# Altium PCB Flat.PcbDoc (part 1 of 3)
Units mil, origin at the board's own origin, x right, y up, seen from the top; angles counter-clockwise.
Board outline 3858.27 x 3228.35 mil, 2 copper layers (Top Layer, Bottom Layer); 95 components, 49 nets, 285 pads, 121 vias.
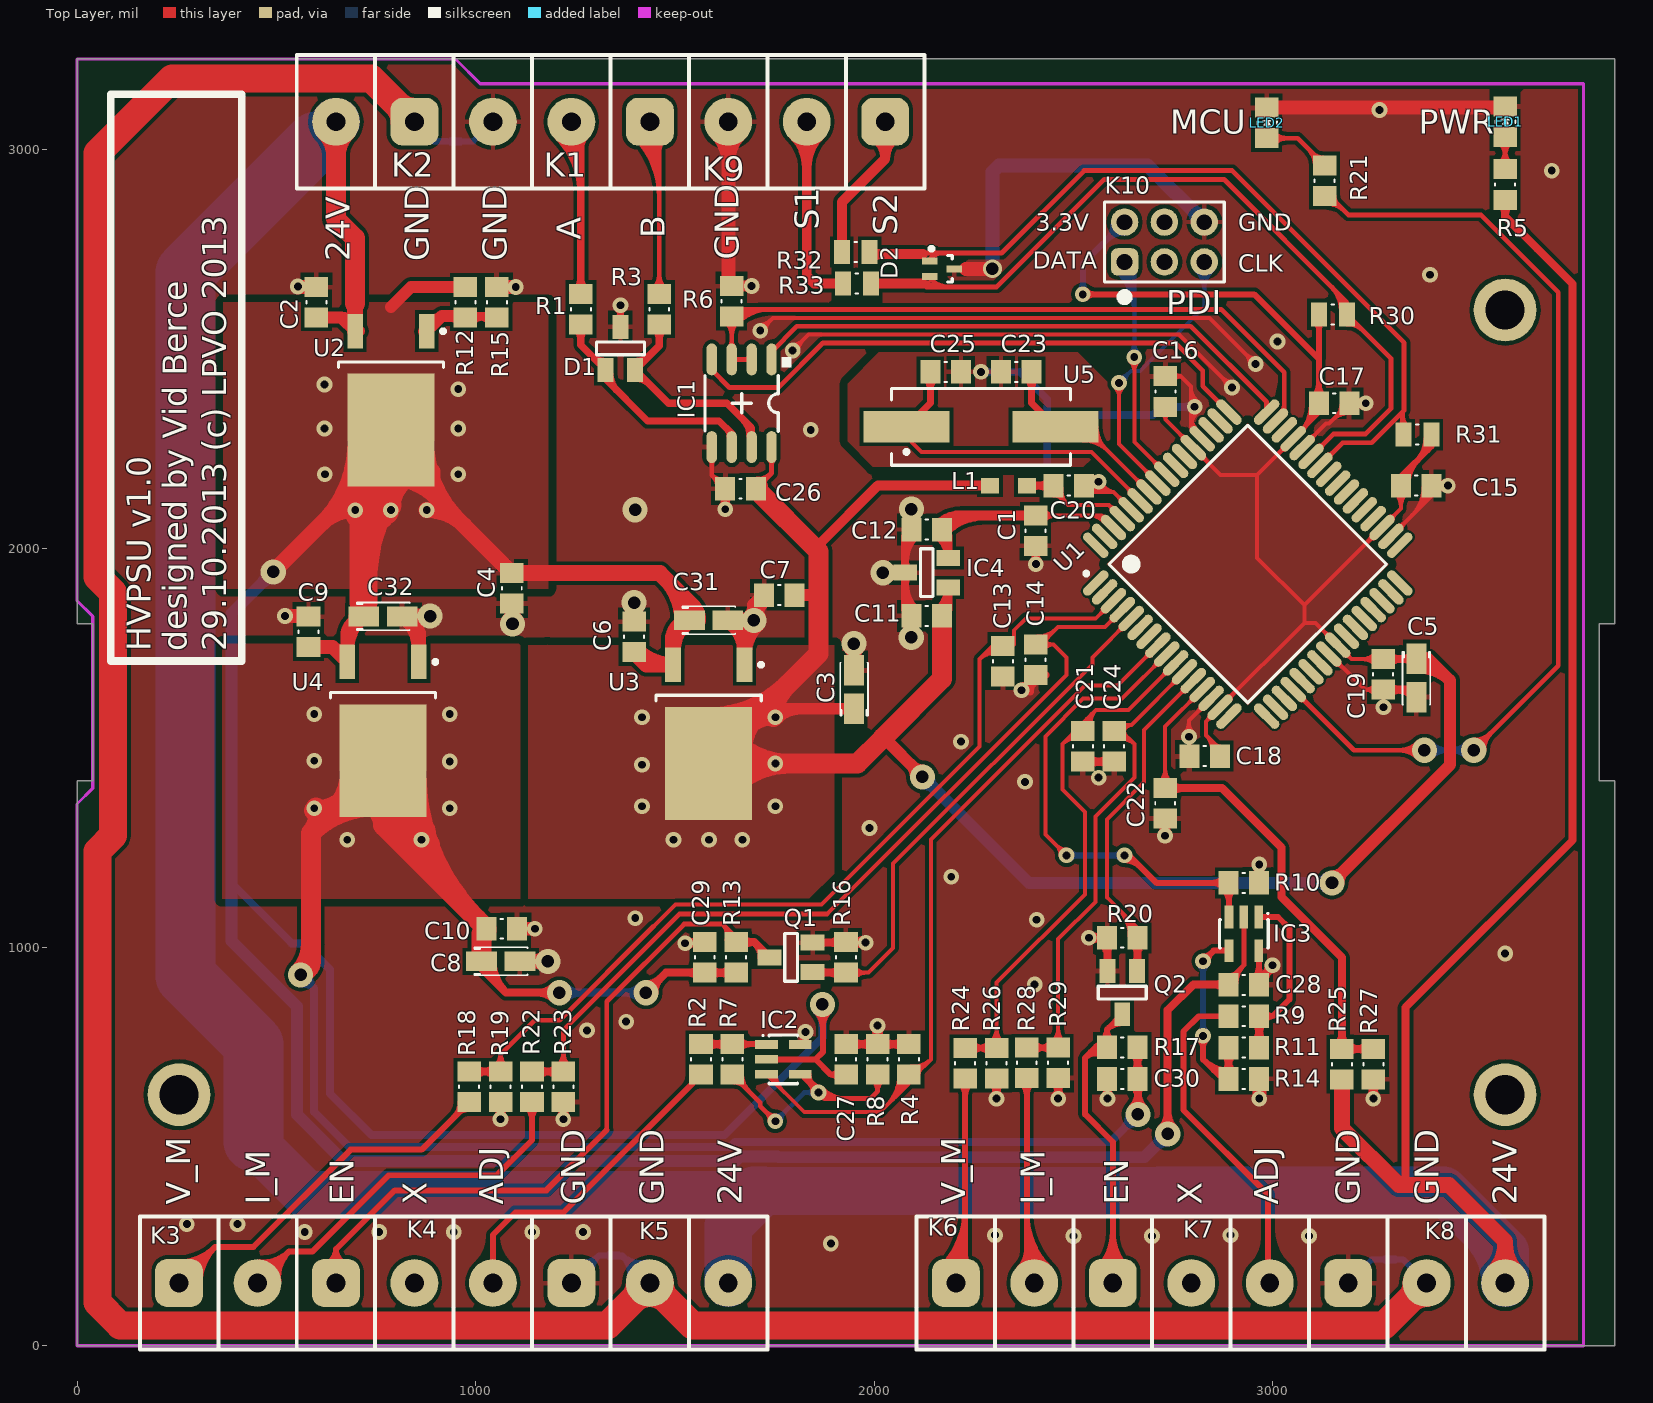
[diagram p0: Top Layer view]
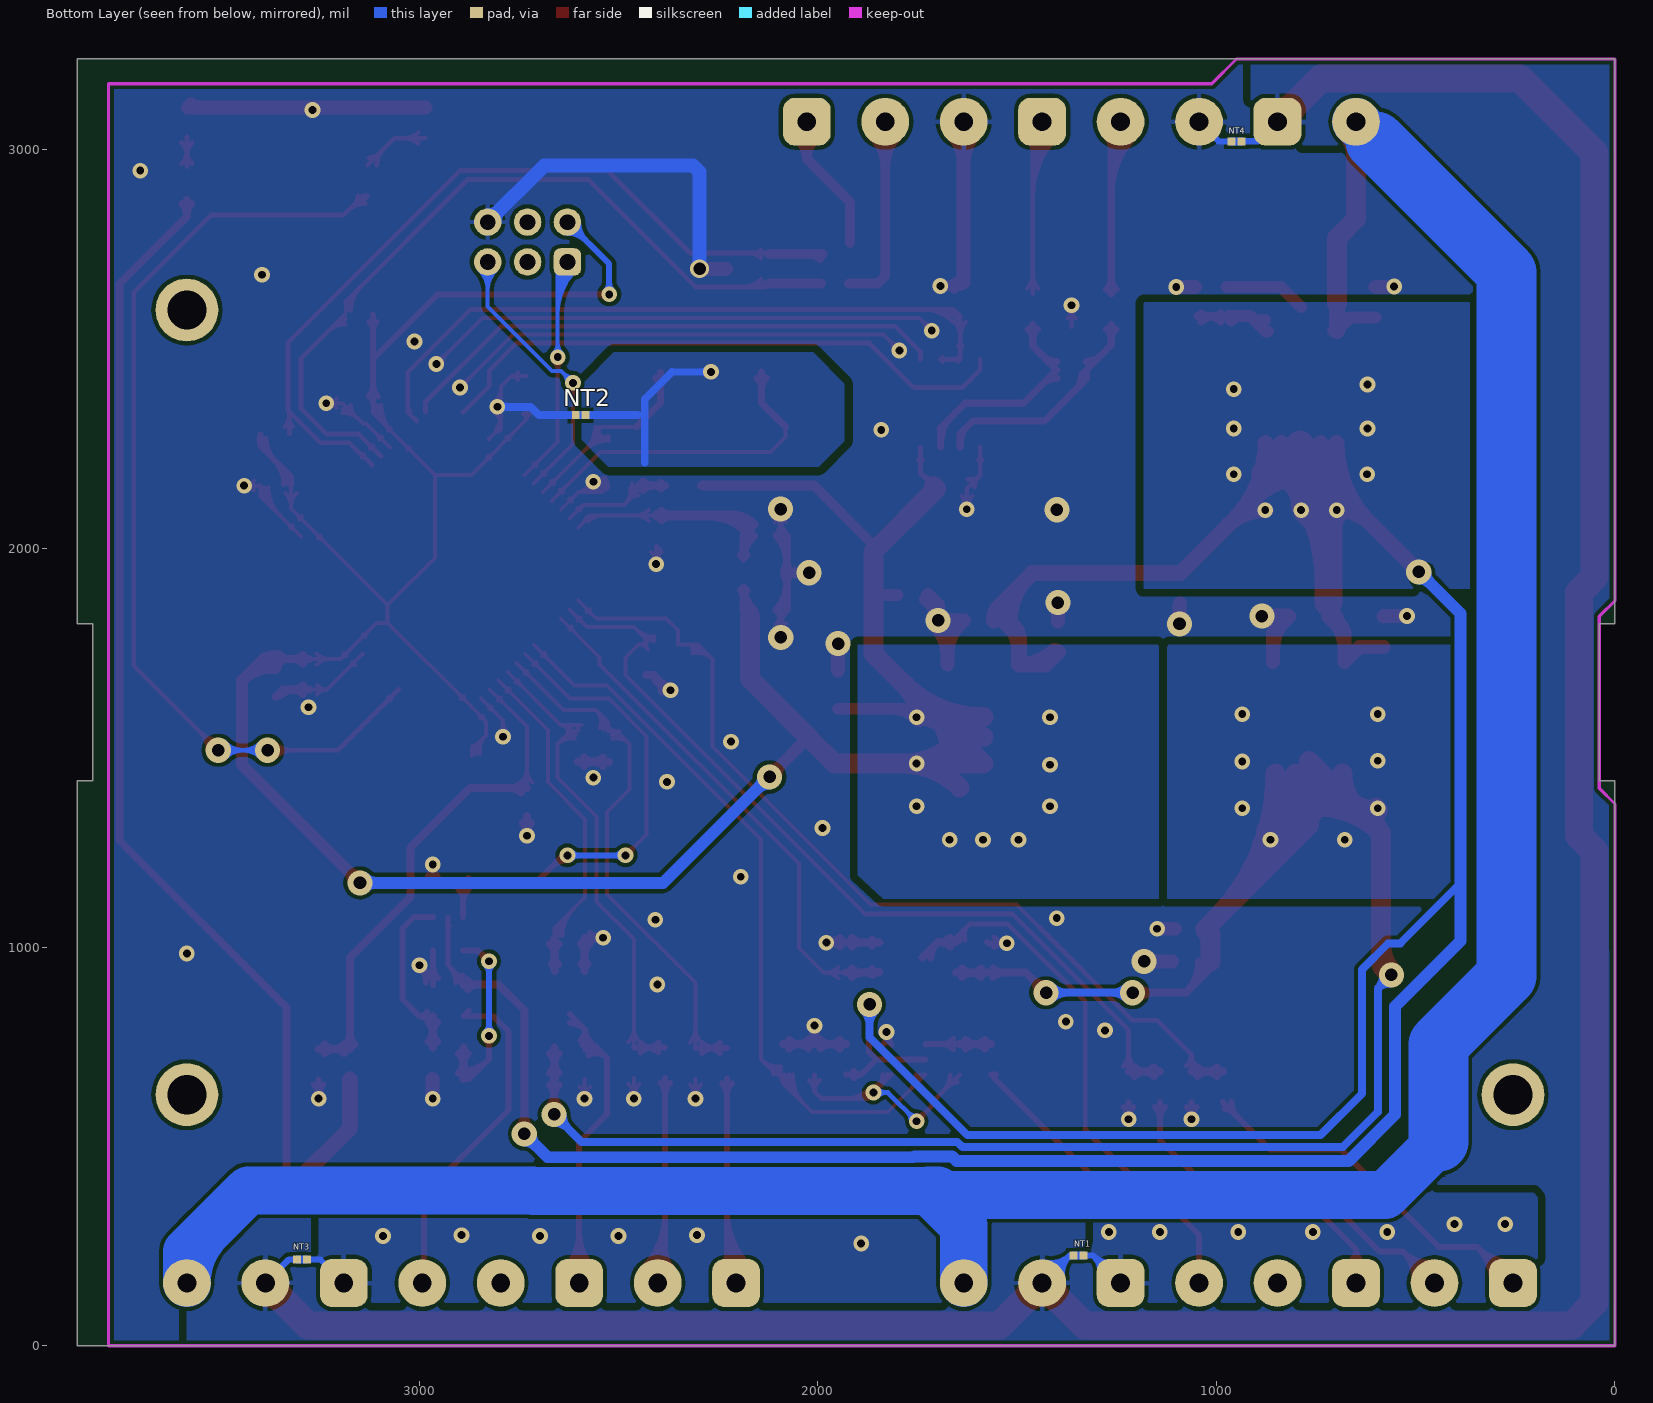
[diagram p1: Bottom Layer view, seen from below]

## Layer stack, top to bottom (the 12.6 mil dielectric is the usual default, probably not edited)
Top Solder: solder mask 0.4, Solder Resist, Dk 3.5
Top Layer: signal copper 1.4
Dielectric1: core 12.6, FR-4, Dk 4.8
Bottom Layer: signal copper 1.4
Bottom Solder: solder mask 0.4, Solder Resist, Dk 3.5

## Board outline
0,0 0,1417.32 39.37,1417.32 39.37,1811.02 0,1811.02 0,3228.35 3858.27,3228.35 3858.27,3228.34 3858.27,1811.02 3818.9,1811.02 3818.9,1417.32 3858.27,1417.32 3858.27,0 0,0

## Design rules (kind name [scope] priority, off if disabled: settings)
Clearance Clearance_poly [InPolygon vs InPolygon] p1: gap=20 ignorepadtopadclearanceinfootprint=FALSE except(0: Arc-Hole Track-Hole SMDPad-Hole THPad-Hole Via-Hole Fill-Hole Poly-Hole Region-Hole Text-Hole)
Clearance Clearance_NET_Join [InComponent('NT1') AND InComponent('NT2') AND InComponent('NT3')] p2: gap=1 ignorepadtopadclearanceinfootprint=FALSE except(0: Arc-Hole Track-Hole SMDPad-Hole THPad-Hole Via-Hole Fill-Hole Poly-Hole Region-Hole Text-Hole)
Clearance MCU_Clearance [InComponent('U1')] p3: gap=6 ignorepadtopadclearanceinfootprint=FALSE except(0: Arc-Hole Track-Hole SMDPad-Hole THPad-Hole Via-Hole Fill-Hole Poly-Hole Region-Hole Text-Hole)
Clearance [All] p4: gap=10 ignorepadtopadclearanceinfootprint=FALSE except(0: Arc-Hole Track-Hole SMDPad-Hole THPad-Hole Via-Hole Fill-Hole Poly-Hole Region-Hole Text-Hole)
ComponentClearance [All] p1 off: gap=10 collisioncheckmode=3 verticalgap=10 showdistances=FALSE
PolygonConnect PolygonConnect_Source [All vs InComponent('U2') OR InComponent('U3') OR InComponent('U4')] p1: connectstyle=Direct reliefconductorwidth=10 reliefentries=4 polygonreliefangle="90 Angle" airgapwidth=10
PolygonConnect PolygonConnect_isVia [All vs isVia] p2: connectstyle=Direct reliefconductorwidth=10 reliefentries=4 polygonreliefangle="90 Angle" airgapwidth=10
PolygonConnect [All] p3: connectstyle=Relief reliefconductorwidth=12 reliefentries=4 polygonreliefangle="90 Angle" airgapwidth=10
RoutingVias GND_VIA [InNet('GND')] p1: holewidth=19.68 width=39.37 viastyle="Through Hole" minholewidth=11.81 minwidth=31.5 maxholewidth=31.5 maxwidth=47.24
RoutingVias [All] p2: holewidth=19.68 width=39.37 viastyle="Through Hole" minholewidth=10 minwidth=31.5 maxholewidth=47 maxwidth=78.74
SolderMaskExpansion [All] p1: expansion=4 istentingtop=FALSE
Width Width_1 [InNet('24V')] p1: maxlimit=200 minlimit=20 preferedwidth=25
Width [All] p2: maxlimit=100 minlimit=10 preferedwidth=12
29 further rules are at their usual default settings.

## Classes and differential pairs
component class U_RS485: C26 D1 IC1 K1 K2 R1 R3 R6
component class U_Power: C2 C3 C4 C5 C6 C7 C8 C9 C10 C11 C12 C15 C16 C17 C18 C19 C20 C31 C32 IC4 L1 LED1 NT4 R5 R12 R15 U2 U3 U4
component class U_Amp: C27 C28 IC2 IC3 R2 R4 R7 R8 R9 R10 R11 R14
component class MCU: C1 C13 C14 C21 C22 C23 C24 C25 C29 C30 D2 K3 K4 K5 K6 K7 K8 K9 K10 LED2 NT1 NT2 NT3 Q1 Q2 R13 R16 R17 R18 R19 R20 R21 R22 R23 R24 R25 R26 R27 R28 R29 R30 R31 R32 R33 U1 U5

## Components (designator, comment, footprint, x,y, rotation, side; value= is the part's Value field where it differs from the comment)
C1 "100n" C0805 2404.95,2044.62 r270 top
C2 "1u/50V" C0805 600.39,2618.11 r90 top
C3 "10u" CT_A 1949.21,1646.46 r90 top
C4 "100n" C0805 1090.68,1900.2 r270 top
C5 "10u" CT_A 3360.28,1675.6 r270 top
C6 "100n" C0805 1397.64,1778.5 r90 top
C7 "100n" C0805 1761.81,1883.49 r180 top
C8 "10u" CT_A 1062.99,964.57 r0 top
C9 "100n" C0805 580.71,1791.34 r90 top
C10 "100n" C0805 1065.68,1046.26 r0 top
C11 "1u" C0805 2131.69,1831.2 r180 top
C12 "1u" C0805 2131.69,2047.73 r180 top
C13 "1n" C0805 2322.83,1717.83 r270 top
C14 "1n" C0805 2404.95,1720.83 r270 top
C15 "100n" C0805 3359.54,2157.89 r0 top
C16 "100n" C0805 2730.36,2394.11 r90 top
C17 "100n" C0805 3153.58,2364.58 r0 top
C18 "100n" C0805 2828.78,1479.15 r180 top
C19 "100n" C0805 3276.45,1684.46 r270 top
C20 "100n" C0805 2487.58,2157.89 r0 top
C21 "1n" C0805 2523.27,1504.15 r270 top
C22 "1n" C0805 2729.96,1360.64 r270 top
C23 "18p" C0805 2356.34,2443.32 r180 top
C24 "1n" C0805 2602.01,1504.15 r270 top
C25 "18p" C0805 2179.17,2443.32 r180 top
C26 "100n" C0805 1664.56,2150.1 r180 top
C27 "100n" C0805 1929.53,718.5 r90 top
C28 "100n" C0805 2927.31,905.51 r0 top
C29 "100n" C0805 1574.8,974.41 r90 top
C30 "100n" C0805 2622.19,669.29 r180 top
C31 "10u/16u" CT_A 1584.65,1819.88 r0 top
C32 "10u/16V" CT_A 767.72,1829.72 r0 top
D1 "CDSOT23-SM712" SOT23(BAT54) 1363.23,2502.38 r0 top
D2 "CDSOT23-SM712" SOT-663 2170.08,2701.85 r0 top
IC1 "EXAR - SP3483EN-L" SO8R 1667.36,2364.58 r180 top value={Value}
IC2 "LMC7101" SO-G5/P.95 1772.05,718.5 r270 top
IC3 "LMC7101" SO-G5/P.95 2927.31,1033.46 r180 top
IC4 "REF3025" SOT23 2131.69,1939.47 r90 top
K1 "CON_3pin_5mm" COM_3pin_5mm 1437.01,3070.87 r180 top
K2 "CON_2pin_5mm" CON_2pin_5mm 846.46,3070.87 r180 top
K3 "CON_2pin_5mm" CON_2pin_5mm 255.91,157.48 r0 top
K4 "CON_3pin_5mm" COM_3pin_5mm 649.61,157.48 r0 top
K5 "CON_3pin_5mm" COM_3pin_5mm 1240.16,157.48 r0 top
K6 "CON_2pin_5mm" CON_2pin_5mm 2204.72,157.48 r0 top
K7 "CON_3pin_5mm" COM_3pin_5mm 2598.43,157.48 r0 top
K8 "CON_3pin_5mm" COM_3pin_5mm 3188.98,157.48 r0 top
K9 "CON_3pin_5mm" COM_3pin_5mm 2027.56,3070.87 r180 top
K10 "H2x3" H2x3 2627.95,2719.07 r180 top
L1 "74279208" SMD-0805 2336.66,2157.89 r180 top
LED1 "LED0805" LED0805 3582.68,3070.87 r90 top value=Green
LED2 "LED0805" LED0805 2984.37,3067.87 r90 top value=yellow
NT1 "NET_TIE" NET_TIE_LINE 1358.27,226.38 r180 bottom net-tie
NT2 "NET_TIE" NET_TIE_LINE 2582.25,2334.85 r0 bottom net-tie
NT3 "NET_TIE" NET_TIE_LINE 3306.54,216.54 r180 bottom net-tie
NT4 "NET_TIE" NET_TIE_LINE 936.88,3021.65 r0 bottom net-tie
Q1 "NX3008NBK" SOT23(IRLML2502) 1791.34,974.41 r90 top value={Value}
Q2 "NX3008NBK" SOT23(IRLML2502) 2622.19,885.83 r180 top value={Value}
R1 "47R" R0805#1 1263.82,2600.8 r90 top
R2 "50E" R0805#1 1565.35,718.5 r270 top
R3 "47R" R0805#1 1460.67,2600.8 r90 top
R4 "100k" R0805#1 2087.01,718.5 r270 top
R5 "12K" R0805#1 3582.68,2913.39 r270 top
R6 "100K" R0805#1 1642.36,2620.49 r270 top
R7 "16k2" R0805#1 1644.09,718.5 r90 top
R8 "11k5" R0805#1 2008.27,718.5 r270 top
R9 "50E" R0805#1 2927.31,826.77 r180 top
R10 "100k" R0805#1 2927.31,1161.42 r180 top
R11 "16k2" R0805#1 2927.31,748.03 r0 top
R12 "13K" R0805#1 974.41,2618.11 r90 top
R13 "10k" R0805#1 1653.54,974.41 r270 top
R14 "11k5" R0805#1 2927.31,669.29 r180 top
R15 "1K5" R0805#1 1053.15,2618.11 r270 top
R16 "100K" R0805#1 1929.13,974.41 r270 top
R17 "10k" R0805#1 2622.19,748.58 r0 top
R18 "12k" R0805#1 983.86,649.61 r270 top
R19 "11k5" R0805#1 1062.6,649.61 r270 top
R20 "100K" R0805#1 2622.19,1023.62 r0 top
R21 "220E" R0805#1 3129.92,2923.23 r90 top
R22 "12k" R0805#1 1141.34,649.61 r270 top
R23 "11k5" R0805#1 1220.08,649.61 r270 top
R24 "12k" R0805#1 2228.09,708.66 r270 top
R25 "11K" R0805#1 3173.37,706.3 r270 top
R26 "11k5" R0805#1 2306.84,708.66 r270 top
R27 "1K" R0805#1 3252.11,706.3 r270 top
R28 "12k" R0805#1 2382.62,709.65 r270 top
R29 "11k5" R0805#1 2461.36,709.65 r270 top
R30 "10k" R0805#2 3150.58,2587.65 r180 top
R31 "10k" R0805#2 3362.54,2285.84 r0 top
R32 "47R" R0805#2 1953.58,2744.07 r180 top
R33 "47R" R0805#2 1956.58,2664.93 r180 top
U1 "ATxmega64A3-AU" 64A_M 2937.05,1961.04 r45 top
U2 "LM317M" TD03B_M 787.4,2372.05 r270 top
U3 "LM1117IDTX-3.3" TD03B_M 1584.65,1535.43 r270 top
U4 "LM1117IDTX-5.0" TD03B_M 767.72,1542.53 r270 top
U5 "8Mhz" HC49/4H_SMX 2267.76,2305.53 r0 top value=8MHz

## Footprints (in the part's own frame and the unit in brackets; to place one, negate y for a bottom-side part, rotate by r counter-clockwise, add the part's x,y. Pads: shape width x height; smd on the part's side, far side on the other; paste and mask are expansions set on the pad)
64A_M [mm] "Thin QFP, 64-Leads, Body 14x14mm, Pitch 0.8mm, IPC Low Density"
  oval 2.05x0.6 smd: 1(-7.7,6) 2(-7.7,5.2) 3(-7.7,4.4) 4(-7.7,3.6) 5(-7.7,2.8) 6(-7.7,2) 7(-7.7,1.2) 8(-7.7,0.4) 9(-7.7,-0.4) 10(-7.7,-1.2) 11(-7.7,-2) 12(-7.7,-2.8) 13(-7.7,-3.6) 14(-7.7,-4.4) 15(-7.7,-5.2) 16(-7.7,-6) 33(7.7,-6) 34(7.7,-5.2) 35(7.7,-4.4) 36(7.7,-3.6) 37(7.7,-2.8) 38(7.7,-2) 39(7.7,-1.2) 40(7.7,-0.4) 41(7.7,0.4) 42(7.7,1.2) 43(7.7,2) 44(7.7,2.8) 45(7.7,3.6) 46(7.7,4.4) 47(7.7,5.2) 48(7.7,6)
  oval 0.6x2.05 smd: 17(-6,-7.7) 18(-5.2,-7.7) 19(-4.4,-7.7) 20(-3.6,-7.7) 21(-2.8,-7.7) 22(-2,-7.7) 23(-1.2,-7.7) 24(-0.4,-7.7) 25(0.4,-7.7) 26(1.2,-7.7) 27(2,-7.7) 28(2.8,-7.7) 29(3.6,-7.7) 30(4.4,-7.7) 31(5.2,-7.7) 32(6,-7.7) 49(6,7.7) 50(5.2,7.7) 51(4.4,7.7) 52(3.6,7.7) 53(2.8,7.7) 54(2,7.7) 55(1.2,7.7) 56(0.4,7.7) 57(-0.4,7.7) 58(-1.2,7.7) 59(-2,7.7) 60(-2.8,7.7) 61(-3.6,7.7) 62(-4.4,7.7) 63(-5.2,7.7) 64(-6,7.7)
  silkscreen extent -7.82,-6.25 6.25,6.97, body extent -7,-7 7,7, height 1.2
C0805 [mm] "Chip Resistor; Body 2 x 1.2 mm (LxW typ)"
  rect 1.275x1.5 smd: 1(-0.975,0) 2(0.975,0)
  silkscreen extent -0.08,-0.64 0.08,0.64, body extent -1,-0.62 1,0.64, height 0.8
COM_3pin_5mm [mil] "Konektor 3 pol Bernic ohišje 5 mm raster Series 605"
  rrect50% 120x120 hole 47.24: 1(0,0)
  round 120 hole 47.24: 2(196.85,0) 3(393.7,0)
  silkscreen extent -98,-167 492,167, body extent -98,-177 492,150, height 551
CON_2pin_5mm [mil] "Series 605 Bernic enclosures"
  rrect50% 120x120 hole 47.24: 1(0,0)
  round 120 hole 47.24: 2(196.85,0)
  silkscreen extent -98,-167 295,167, body extent -98,-177 295,150, height 551
CT_A [mm] "Molded Capacitor, 2-Leads, Body 3,2x1,6mm, IPC Medium Density"
  rect 1.95x1.25 smd: 1(-1.225,0) 2(1.225,0)
  silkscreen extent -1.68,-0.89 1.7,0.89, body extent -1.6,-0.81 1.6,0.79, height 1.63
H2x3 [mm]
  rrect50% 1.75x1.75 hole 1: 1(0,0)
  round 1.75 hole 1: 2(0,-2.54) 3(-2.54,0) 4(-2.54,-2.54) 5(-5.08,0) 6(-5.08,-2.54)
  silkscreen extent -6.35,-3.81 1.27,1.27, body extent -6.35,-3.81 1.27,1.27, height 8.4
HC49/4H_SMX [mm]
  rect 5.5x2 smd: 1(-4.75,0) 2(4.75,0)
  silkscreen extent -5.7,-2.45 5.7,2.45, body extent -6.2,-2.4 6.2,2.43, height 4.26
LED0805 [mm] "Chip Resistor; Body 2 x 1.2 mm (LxW typ)"
  rect 1.275x1.5 smd: A(-0.975,0) K(0.975,0)
  silkscreen extent -0.19,-0.66 0.19,0.61, body extent -1.03,-0.45 1.03,0.46, height 0.86
NET_TIE_LINE [mm] "Line to tie two nets"
  rect 0.5x0.5 smd: 1(0,0) 2(0.635,0)
  Top Layer lines w0.5: 0.635,0 0,0
R0805#1 [mm] "Chip Resistor; Body 2 x 1.2 mm (LxW typ)"
  rect 1.275x1.5 smd: 1(-0.975,0) 2(0.975,0)
  silkscreen extent -0.08,-0.64 0.08,0.64, body extent -1,-0.62 1,0.64, height 0.8
R0805#2 [mm] "Chip Resistor; Body 2 x 1.2 mm (LxW typ)"
  rect 1.016x1.524 smd: 1(-0.889,0) 2(0.889,0)
  silkscreen extent -0.08,-0.64 0.08,0.64, body extent -1,-0.62 1,0.64, height 0.8
SMD-0805 [mm] "Chip Inductor, 2-Leads, Body 2.0x1.2mm"
  rect 1.15x1 smd: 1(-1.175,0) 2(1.175,0)
  body extent -1,-0.6 1,0.6, height 1.1
SO8R [mil]
  oval 26x80 smd: 1(-75,-110) 2(-25,-110) 3(25,-110) 4(75,-110) 5(75,110) 6(25,110) 7(-25,110) 8(-75,110)
  silkscreen extent -125,-115 92,70, body extent -97,-120 96,118, height 65
SO-G5/P.95 [mm]
  rect 0.55x1.45 smd: 1(-0.95,-1.075) 2(0,-1.075) 3(0.95,-1.075) 4(0.95,1.075) 5(-0.95,1.075)
  silkscreen extent -1.57,-1.35 1.55,0.9, body extent -1.5,-1.5 1.5,1.5, height 1.3
SOT23 [mil]
  rect 40x60 smd: 1(-37,-54) 2(37,-54) 3(0,54)
  silkscreen extent -60,-16 60,16, body extent -57,-46 57,46, height 39
SOT23(BAT54) [mil]
  rect 40x60 smd: 1(-37,-54) 2(37,-54) 3(0,54)
  silkscreen extent -60,-16 60,16, body extent -57,-46 58,46, height 39
SOT23(IRLML2502) [mil]
  rect 40x60 smd: D(0,54) G(-37,-54) S(37,-54)
  silkscreen extent -60,-16 60,16, body extent -57,-46 57,46, height 39
SOT-663 [mm] "SOT663 3-Leads, Body 1,60x1,20mm, Pitch 0,50mm, IPC Low Density"
  rect 1x0.45 smd: 1(-0.777,0.5) 2(-0.777,-0.5) 3(0.787,0)
  silkscreen extent -0.8,-0.85 0.65,1.4, body extent -0.65,-0.85 0.65,0.85, height 0.6
TD03B_M [mm] "D-PAK, 4-Leads, Body 6.1x6.6mm, Pitch 2.29mm, Lead Span 9.7mm, IPC Low Density"
  rect 2.2x1 smd: 1(-4.4,2.28) 3(-4.4,-2.28)
  rect 7.2x5.55 smd: 4(1.9,0)
  silkscreen extent -4.52,-3.35 -2.1,3.46, body extent -2.45,-3.35 3.75,3.35, height 2.38

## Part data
C1 C2 C4 C6 C7 C9 C10 C11 C12 C13 C14 C15 C16 C17 C18 C19 C20 C21 C22 C23 C24 C25 C26 C27 C28 C29 C30: library part "SMD CAPACITOR", "SMD Chip Capacitor", Tolerance={Tolerance}
C3 C5 C8 C31 C32: library part CT_A, "{Description}", MaxLeakageCurrent={MaxLeakageCurrent}, MinRippleCurrent={MinRippleCurrent}, TempRange={TempRange}, Tolerance={Tolerance}
D2: library part BAT54A, PackageDocument=May-1999, Supplier Part Number 1=1824869
IC1: library part MAX485CSA_(SO8), "Line-Powered RS-232 Transceiver Chip", Supplier Part Number 1=1296640
IC2 IC3: Supplier Part Number 1=2100273
IC4: library part REF3040, "REF3040", Supplier Part Number 1=1470324
K1 K4 K5 K7 K8 K9: "Konektor za Bernic ohišja, 5 mm"
K2 K3 K6: "Konektor za  Bernic ohišja Serija 605, 5 mm raster"
K10: "Header 2x3 (male)"
L1: "SMD EMI Suppression Ferrite Bead WE-CBF, Z = 40 Ohm"
LED1 LED2: "Chip LED diode"
Q1 Q2: library part IRLML2502, "IRLML2502", Supplier Part Number 1=2069541
R1 R2 R3 R4 R5 R6 R7 R8 R9 R10 R11 R12 R13 R14 R15 R16 R17 R18 R19 R20 R21 R22 R23 R24 R25 R26 R27 R28 R29 R30 R31 R32 R33: library part "SMD RESISTOR", "Surface mount resistor", Power={Power}
U1: "8/16-bit AVR XMEGA A3 Microcontroller, 1.6-3.6V, 32MHz, 64KB + 4KB Flash, 2KB EEPROM, 4KB SRAM, 64-pin TQFP, Industrial Grade (-40°C to 85°C), Pb-Free", Supplier Part Number 1=2066311
U2: library part LM317MDT, "3-Terminal Adjustable Regulator, 3-pin TO-252", Manufacturer="National Semiconductor", PackageTopMarking=NSUZXYTT*LM317*MDT, PowerWise=N, Supplier Part Number 1=2296022
U3: "800mA Low-Dropout Linear Regulator, 3-pin TO-252", Manufacturer="National Semiconductor", PackageTopMarking=NSUZXYTT*LM1117*IDT-3.3, PowerWise=N, Supplier Part Number 1=1469048
U4: "800mA Low-Dropout Linear Regulator, 3-pin TO-252", Manufacturer="National Semiconductor", PackageTopMarking=NSUZXYTT*LM1117*IDT-5.0, PowerWise=N, Supplier Part Number 1=1685604
U5: library part "Q HC49 SMD", "Q SMD", PackageDocument=18-Oct-1999, Supplier Part Number 1=1611765

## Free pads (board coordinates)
  round 157.48 hole 98.43: 0(255.91,629.92) 0(3582.68,629.92) 0(3582.68,2598.43)

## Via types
v1: diameter 39.37, hole 19.68, Top Layer to Bottom Layer, 99 vias
v2: diameter 62.99, hole 31.5, Top Layer to Bottom Layer, 21 vias
v3: diameter 47.24, hole 31.5, Top Layer to Bottom Layer, 1 vias

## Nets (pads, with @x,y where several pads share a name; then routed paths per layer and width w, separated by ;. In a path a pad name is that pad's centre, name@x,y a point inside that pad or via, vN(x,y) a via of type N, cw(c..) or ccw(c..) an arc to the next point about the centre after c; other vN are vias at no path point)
2.5V: C1.1 C12.1 IC4.2 U1.62 | length 1070.8
  Top Layer w10: C1.1@2404.95,2083.01 2570.1,2083.01 ; C1.1@2423.59,2068.79 cw(c2457.9,2034.48) 2457.9,2083.01 cw(c2457.9,2131.53) C1.1@2423.59,2097.22 ; 2539.63,2083.01 cw(c2539.63,2032.7) U1.62@2575.2,2068.27 ; 2563.77,2083.01 cw(c2563.77,2056.85) U1.62@2582.27,2075.34 ; U1.62@2573.25,2073.9 ccw(c2562.3,2075.2) 2570.1,2083.01 ; U1.62@2579.21,2079.85 cw(c2577.9,2090.81) 2570.1,2083.01 ; U1.62@2600.2,2052.91 2570.1,2083.01
  Top Layer w20: C12.1@2160.02,2032.05 cw(c2108.75,1974.67) IC4.2@2185.69,1974.67 ; C12.1@2170.08,2047.73 2185.69,2032.12 IC4.2@2185.69,1976.47 ; C12.1@2173.35,2046.96 cw(c2148.69,2019.37) C12.1@2185.69,2019.37 ; IC4.2@2178.62,1983.54 ccw(c2161.55,2000.61) 2185.69,2000.61 ccw(c2209.84,2000.61) IC4.2@2192.77,1983.54
  Top Layer w25: C12.1@2161.31,2060.93 cw(c2214.6,2007.64) 2214.6,2083.01 ; C12.1@2170.08,2047.73 2205.35,2083.01 C1.1@2404.95,2083.01 ; C12.1@2170.08,2064.76 ccw(c2170.08,2105.87) 2199.15,2076.8 ; C12.1@2178.99,2043.25 cw(c2274.96,1947.29) 2274.96,2083.01 ; C1.1@2391.61,2074.1 ccw(c2370.1,2052.59) 2370.1,2083.01 ccw(c2370.1,2113.42) C1.1@2391.61,2091.91
3.3V: C3.1 C5.1 C7.1 C11.1 C15.1 C16.1 C17.1 C18.1 C19.1 C26.1 IC1.8 IC4.1 K10.2 L1.2 R30.2 R31.2 U1.15 U1.25 U1.35 U1.45 U1.53 U3.4 | length 10973
  Top Layer w10: C16.1@2721.58,2337.64 cw(c2714.78,2323.63) 2730.36,2323.63 ; C16.1@2730.36,2355.72 2730.36,2323.63 ; C16.1@2739.13,2337.64 ccw(c2745.93,2323.63) 2730.36,2323.63 ; U1.53@2773.64,2273.53 ccw(c2757.2,2273.53) 2768.83,2285.16 ccw(c2780.46,2296.78) U1.53@2780.46,2280.34 ; U1.53@2820.82,2226.35 cw(c2820.82,2209.91) 2832.45,2221.54 cw(c2844.08,2233.16) U1.53@2827.63,2233.16 ; U1.15@2840.46,1581.73 cw(c2824.01,1581.73) 2835.64,1570.11 cw(c2847.27,1558.48) U1.15@2847.27,1574.92 ; 2846,1518.25 cw(c2818.13,1490.38) C18.1@2857.16,1484.97 ; C18.1@2847.26,1486.34 ccw(c2793.17,1493.85) 2831.78,1532.46 ; C18.1@2855.9,1508.34 ccw(c2867.17,1519.61) C18.1@2867.17,1503.68 ; C18.1@2867.17,1479.15 2867.17,1497.08 2831.78,1532.46 ; U1.15@2867.45,1601.92 2831.78,1566.25 2831.78,1532.46 ; U1.15@2868.84,1603.31 3078.93,1813.4 ; U1.15@2887.63,1628.91 ccw(c2887.63,1645.35) 2899.26,1633.73 ccw(c2910.89,1622.1) U1.15@2894.45,1622.1 ; U1.45@3024.19,2255.43 cw(c3007.75,2255.43) 3019.38,2243.81 cw(c3031,2232.18) U1.45@3031,2248.62 ; U1.45@3049.8,2274.23 2960.71,2185.14 ; U1.45@3051.19,2275.62 3115.2,2339.63 C17.1@3115.2,2364.58 ; U1.45@3066.38,2290.8 ccw(c2997.03,2360.15) C17.1@3095.1,2360.15 ; U1.45@3071.37,2302.61 ccw(c3071.37,2319.05) 3083,2307.43 ccw(c3094.63,2295.8) U1.45@3078.18,2295.8 ; 3083.45,2307.88 ccw(c3031.17,2360.15) C17.1@3105.1,2360.15 ; 3100.52,2324.95 ccw(c3065.31,2360.15) C17.1@3115.1,2360.15 ; 3130.53,1790.12 cw(c3118.41,1778) U1.25@3135.55,1778 ; 3131.22,1789.42 ccw(c3142.36,1800.56) U1.25@3142.36,1784.81 ; U1.25@3182.73,1730.82 cw(c3182.73,1714.38) 3194.35,1726 cw(c3205.98,1737.63) U1.25@3189.54,1737.63 ; U1.35@3246.9,2032.72 cw(c3230.46,2032.72) 3242.09,2021.1 cw(c3253.72,2009.47) U1.35@3253.72,2025.91 ; C19.1@3257.81,1708.64 ccw(c3223.5,1674.33) 3223.5,1722.85 ccw(c3223.5,1771.37) C19.1@3257.81,1737.06 ; U1.35@3272.51,2051.51 3078.93,1857.94 ; U1.35@3273.9,2052.91 3321.16,2100.17 C15.1@3321.16,2157.89 ; C19.1@3276.45,1722.85 3197.51,1722.85 3161.15,1759.21 3161.15,1759.49 3107.25,1813.4 3078.93,1813.4 ; U1.35@3294.08,2079.9 ccw(c3294.08,2096.34) 3305.71,2084.72 ccw(c3317.34,2073.09) U1.35@3300.89,2073.09 ; C15.1@3306.95,2139.25 cw(c3272.64,2104.94) 3321.16,2104.94 cw(c3369.68,2104.94) C15.1@3335.37,2139.25 ; 2730.36,2323.63 2868.84,2185.14 2960.71,2185.14 ; 2960.71,2185.14 2960.71,1976.17 3078.93,1857.94 ; 3078.93,1813.4 3078.93,1857.94
  Top Layer w12: C26.1@1703.21,2173.63 ccw(c1703.98,2227.91) 1742.36,2189.52 ; C26.1@1708.35,2155.51 1742.36,2189.52 ; C26.1@1722.04,2154.53 cw(c1757.45,2154.53) 1732.41,2179.57 ; IC1.8@1737.41,2222.63 cw(c1725.46,2210.68) 1742.36,2210.68 cw(c1759.26,2210.68) IC1.8@1747.31,2222.63 ; IC1.8@1742.36,2254.58 1742.36,2189.52
  Top Layer w15: v1(2523.27,2637.8) 2953.24,2637.8 3115.2,2475.84 C17.1@3115.2,2364.58 ; v1@2531.89,2629.18 cw(c2552.69,2608.38) 2552.69,2637.8 cw(c2552.69,2667.21) v1@2531.89,2646.41 ; C17.1@3102.75,2381.45 ccw(c3072.71,2411.5) 3115.2,2411.5 ccw(c3157.68,2411.5) C17.1@3127.64,2381.45 ; R30.2@3106.75,2568.81 cw(c3085.41,2547.48) 3115.58,2547.48 cw(c3145.76,2547.48) R30.2@3124.42,2568.81 ; 3115.58,2476.22 R30.2@3115.58,2587.65 ; C15.1@3321.16,2157.89 3321.16,2179.79 3397.54,2256.18 R31.2@3397.54,2285.84 ; C15.1@3323.76,2162.32 cw(c3372.22,2162.32) 3337.95,2196.59 ; C15.1@3338.76,2162.32 cw(c3423.43,2162.32) 3363.56,2222.19 ; 3362.3,2220.94 ccw(c3307.4,2275.84) R31.2@3385.04,2275.84 ; 3387.91,2246.54 ccw(c3358.61,2275.84) R31.2@3400.04,2275.84
  Top Layer w20: C11.1@2160.25,1847.08 ccw(c2112.71,1902.46) IC4.1@2185.69,1902.47 2185.69,1846.81 C11.1@2170.08,1831.2 ; C11.1@2173.27,1831.91 ccw(c2150.07,1858.94) C11.1@2185.69,1858.94 ; IC4.1@2178.62,1895.4 cw(c2161.55,1878.32) 2185.69,1878.32 cw(c2209.84,1878.32) IC4.1@2192.77,1895.4 ; C19.1@3276.45,1722.85 3359.29,1722.85 C5.1@3360.28,1723.83 ; C19.1@3291.56,1712.17 cw(c3317.33,1686.4) 3317.33,1722.85 cw(c3317.33,1759.3) C19.1@3291.56,1733.53 ; 3322.64,1722.85 ccw(c3322.64,1761.47) C5.1@3349.95,1734.16 ; 3327.39,1722.85 cw(c3327.39,1690.95) C5.1@3349.95,1713.5
  Top Layer w25: 1860.24,1992.81 1860.24,2009.19 2008.94,2157.89 L1.2@2290.4,2157.89
  Top Layer w30: v1@1755.28,1573.58 cw(c1814.79,1514.08) 1814.79,1598.23 ; 1773.82,1598.23 C3.1@1949.21,1598.23 ; C7.1@1800.2,1883.49 1856.67,1883.49 ; 2023.17,1526.32 v2@2117.16,1432.32 ; 2091.68,1457.8 cw(c2061.05,1427.17) v2@2104.37,1427.17 ; 2095.18,1454.3 ccw(c2120.87,1479.99) v2@2120.87,1443.66 ; v2(3148.37,1161.42) 3444.88,1457.93 3444.88,1668.73 ; v2@3148.37,1177.91 ccw(c3148.37,1217.74) 3176.53,1189.58 ccw(c3204.69,1161.42) v2@3164.87,1161.42 ; C5.1@3358.99,1730.41 cw(c3362.17,1679.97) 3397.91,1715.71 ; C5.1@3360.88,1700.47 cw(c3367.75,1591.6) 3444.88,1668.73 ; 3389.78,1723.83 3444.88,1668.73
  Top Layer w50: U3.4@1584.65,1527.36 ccw(c1584.65,1688.47) 1698.56,1574.55 ; U3.4@1584.65,1577.36 ccw(c1584.65,1859.18) 1783.92,1659.9 ; U3.4@1644.22,1401.05 cw(c1788.05,1257.23) 1788.05,1460.63 cw(c1788.05,1664.03) U3.4@1644.22,1520.2 ; U3.4@1668.9,1493.11 cw(c1793.89,1493.11) 1705.51,1581.49 ; U3.4@1673.88,1549.87 cw(c1751.97,1471.78) v1@1751.97,1582.21 ; C26.1@1708.35,2155.51 C26.1@1702.94,2150.1 1860.24,1992.81 1860.24,1736.22 U3.4@1584.65,1460.63 1957.48,1460.63 2023.17,1526.32 ; v1@1746.65,1576.9 cw(c1857.08,1576.9) 1779,1654.98 ; 2022.44,1525.59 2170.08,1673.23 C11.1@2170.08,1831.2
  Bottom Layer w15: v1@2514.65,2646.41 ccw(c2493.85,2667.21) 2523.27,2667.21 ccw(c2552.69,2667.21) v1@2531.89,2646.41 ; v1(2523.27,2637.8) 2523.27,2714.39 K10.2@2627.95,2819.07 ; K10.2@2601,2819.07 cw(c2535.94,2819.07) 2581.95,2773.07 cw(c2627.95,2727.06) K10.2@2627.95,2792.12
  Bottom Layer w30: v2@2120.87,1410.67 cw(c2120.87,1367.35) 2151.5,1397.98 ; v2@2134.69,1414.79 2388.06,1161.42 v2(3148.37,1161.42) ; v2@2137.36,1427.17 ccw(c2173.69,1427.17) 2148,1401.48 ; v2@3136.71,1149.75 ccw(c3108.55,1121.59) 3108.55,1161.42 ccw(c3108.55,1201.24) v2@3136.71,1173.08
  other v1: 1496.25,1269.68 1585.63,1269.68 1669.09,1269.68 1417.32,1353.43 1751.97,1353.43 1417.32,1457.88 1751.97,1460.63 1417.32,1576.9 1751.97,1576.9
  other v2: 2120.87,1427.17
5V: C8.1 C10.1 C29.1 C30.1 R13.2 R17.2 U4.4 | length 7828
  Top Layer w20: C8.1@1014.76,964.57 1014.76,947.51 1076.45,885.83 v2(1210.16,885.83) ; C8.1@1023.15,964.57 ccw(c1084.58,964.57) 1041.14,921.13 ; C8.1@1043.15,964.57 ccw(c1152.86,964.57) 1075.28,886.99 ; v2@1194.96,870.63 ccw(c1158.26,833.93) 1158.26,885.83 ccw(c1158.26,937.72) v2@1194.96,901.03 ; v2(1427.17,885.83) 1477.36,936.02 C29.1@1574.8,936.02 R13.2@1653.54,936.02 ; v2@1427.17,907.32 ccw(c1427.17,959.22) 1463.86,922.52 ccw(c1500.56,885.83) v2@1448.66,885.83 ; C29.1@1559.7,925.35 ccw(c1533.92,899.57) 1533.92,936.02 ccw(c1533.92,972.47) C29.1@1559.7,946.7 ; C29.1@1589.91,925.35 cw(c1615.68,899.57) 1615.68,936.02 cw(c1615.68,972.47) C29.1@1589.91,946.7 ; R13.2@1638.44,925.35 ccw(c1612.66,899.57) 1612.66,936.02 ccw(c1612.66,972.47) R13.2@1638.44,946.7 ; v2@2646.42,595.91 ccw(c2609.72,632.6) 2661.62,632.6 ccw(c2713.51,632.6) v2@2676.82,595.91 ; C30.1@2649.9,654.19 cw(c2621.61,625.89) 2661.62,625.89 ; C30.1@2649.9,684.4 ccw(c2624.12,710.17) 2660.57,710.17 ccw(c2697.03,710.17) C30.1@2671.25,684.4 ; R17.2@2649.9,733.48 cw(c2624.12,707.7) 2660.57,707.7 cw(c2697.03,707.7) R17.2@2671.25,733.48 ; R17.2@2660.57,748.58 C30.1@2660.57,669.29 2661.62,668.25 v2(2661.62,580.71) ; 2661.62,630.93 cw(c2694.51,630.93) C30.1@2671.25,654.19
  Top Layer w50: v2@556.43,935.16 ccw(c483.3,1008.29) 586.72,1008.29 ; v2@560.67,937.05 ccw(c559.17,964.57) 586.72,964.57 586.72,1286.73 ; v2(561.02,930.57) 561.02,937.67 586.72,963.36 ; 586.73,1286.74 cw(c744.06,1129.41) U4.4@761.22,1351.25 ; v1@594.93,1343.11 ccw(c594.93,1459.39) U4.4@677.15,1377.17 ; v1@599.87,1350.39 cw(c544.9,1328.56) 586.72,1286.74 ; 646.86,1346.87 ccw(c558.48,1435.25) U4.4@683.46,1435.25 ; U4.4@663.56,1363.57 cw(c755.09,1272.04) U4.4@765.08,1401.1 ; U4.4@733.63,1358.2 cw(c710.46,1305.84) 767.72,1305.84 ; U4.4@751.97,1435.25 ccw(c1026.39,1435.25) 832.34,1241.21 ; 770.3,1303.25 ccw(c864.17,1397.13) v1@864.17,1264.37 ; U4.4@801.81,1358.2 ccw(c824.98,1305.84) 767.72,1305.84 ; U4.4@801.97,1435.25 ccw(c1197.1,1435.25) 917.7,1155.85 ; 832.3,1301.66 ccw(c891.18,1318.72) v1@861.61,1265.03 ; 836.72,1286.42 ccw(c866.17,1294.96) v1@863.75,1264.39 ; U4.4@851.97,1435.25 ccw(c1367.81,1435.25) C10.1@1003.05,1070.5 ; v1@858.86,1269.69 ccw(c991.62,1269.68) 897.74,1175.81 ; v1@858.92,1270.5 ccw(c927.31,1259.91) 871.46,1219.04 ; v1@865.76,1274.76 cw(c855.43,1241.68) 886.12,1257.77 ; v1@868.48,1266.57 ccw(c839.2,1287.71) 874.86,1293.47 ; C8.1@1014.76,964.57 1014.76,1033.73 C10.1@1027.29,1046.26 767.72,1305.83 ; 1014.76,1011.35 cw(c1057.77,1011.35) C10.1@1027.36,1041.76 ; 586.72,1286.73 U4.4@767.72,1467.73 767.72,1305.83
  Bottom Layer w20: v2(561.02,930.57) 594.93,896.66 ; v2@562.26,909.11 cw(c564.71,866.44) 594.93,896.66 ; v2@582.48,929.33 ccw(c625.15,926.88) 594.93,896.66 ; v2(1210.16,885.83) v2(1427.17,885.83) ; v2@1225.36,870.63 cw(c1262.05,833.93) 1262.05,885.83 cw(c1262.05,937.72) v2@1225.36,901.03 ; v2@1411.97,870.63 ccw(c1375.27,833.93) 1375.27,885.83 ccw(c1375.27,937.72) v2@1411.97,901.03 ; v2@2640.12,580.71 cw(c2588.23,580.71) 2624.92,544.01 cw(c2661.62,507.32) v2@2661.62,559.21 ; v2(2661.62,580.71) 2592.41,511.5 1650.06,511.5 1637.17,498.6 1191.21,498.6 1191.04,498.78 1091.63,498.78 1091.46,498.6 682.78,498.6 594.93,586.46 594.93,896.66
  other v1: 677.95,1269.68 864.17,1269.68 594.93,1348.43 935.04,1348.43 935.04,1465.63 594.93,1467.73 594.93,1584.65 935.04,1584.65
12V: C4.1 C6.1 C9.1 C27.1 C28.1 C31.1 C32.1 IC2.2 IC3.2 R12.2 U2.4 U3.3 U4.3 | length 12437.1
  Top Layer w12: C28.1@2888.92,905.51 2888.92,916.34 2927.31,954.72 IC3.2@2927.31,1075.79 ; C28.1@2888.92,929.04 ccw(c2888.92,959.7) 2910.6,938.02 ; C28.1@2896.02,909.94 cw(c2928.6,909.94) C28.1@2905.56,932.98 ; C28.1@2908.02,909.94 cw(c2969.57,909.94) 2926.05,953.47 ; IC3.2@2923.89,1054.66 cw(c2915.65,1046.42) 2927.31,1046.42 cw(c2938.96,1046.42) IC3.2@2930.72,1054.66
  Top Layer w15: IC2.2@1729.72,718.5 1852.76,718.5 ; v2@1853.11,839.33 cw(c1810.25,796.47) 1870.87,796.47 ; 1870.87,800.27 cw(c1926.11,800.27) v2@1887.05,839.33 ; v2@1870.87,855.51 1870.87,736.61 1852.76,718.5 ; C27.1@1910.72,669.97 ccw(c1891.14,656.16) 1891.14,680.12 ; C27.1@1910.72,690.26 cw(c1891.14,704.08) 1891.14,680.12 ; C27.1@1929.53,680.12 1891.14,680.12 ; 1852.76,718.5 1891.14,680.12
  Top Layer w20: v2@2721.02,546.7 ccw(c2684.32,583.39) 2736.22,583.39 ccw(c2788.12,583.39) v2@2751.42,546.7 ; v2(2736.22,531.5) 2736.22,842.08 2800.64,906.5 2887.94,906.5 C28.1@2888.92,905.51 ; 2850.09,906.5 cw(c2850.09,866.69) C28.1@2878.25,894.84 ; 2854.85,906.5 ccw(c2854.85,939.59) C28.1@2878.25,916.19
  Top Layer w30: 787.4,2605.64 838.25,2656.5 R12.2@974.41,2656.5
  Top Layer w35: C9.1@580.71,1752.95 640.76,1752.95 ; U4.3@677.55,1741.53 cw(c670.01,1782.2) 640.76,1752.95 ; U4.3@677.95,1745.56 cw(c789.87,1745.56) C32.1@710.73,1824.7 ; 677.95,1779.77 cw(c724.07,1779.77) C32.1@708.16,1823.05 ; 683.83,1794.07 ccw(c648.18,1829.72) C32.1@698.6,1829.72 ; 718.79,1865.16 719.49,1864.46 C32.1@719.49,1829.72 677.95,1788.19 U4.3@677.95,1715.76 640.76,1752.95
  Top Layer w40: v2(492.13,1941.53) 708.49,2157.89 ccw(c747.01,2119.36) v1@697.64,2096.32 ; 611.63,2061.03 cw(c697.92,1974.73) v1@697.92,2096.77 ; 615.27,2064.67 ccw(c415.17,2264.76) U2.4@698.15,2264.76 ; 682.77,2132.17 cw(c787.4,2027.54) 787.4,2175.51 cw(c787.4,2015.34) 900.66,2128.6 ; 683.55,2132.95 ccw(c551.74,2264.76) U2.4@738.15,2264.76 ; U2.4@792.29,2175.65 cw(c799.43,2045.5) 891.59,2137.67 ; U2.4@836.65,2264.76 ccw(c1010.86,2264.76) 887.68,2141.58 ; U2.4@870.93,2233.33 ccw(c955.45,2201.52) 891.6,2137.66 ; U2.4@876.65,2264.76 ccw(c1147.42,2264.76) 955.96,2073.3 ; v1@877.17,2096.77 cw(c877.17,1963.21) 971.61,2057.65 ; U2.4@891.6,2193.05 891.6,2137.66 ; C6.1@1397.64,1740.11 1429.09,1708.66 U3.3@1494.88,1708.66 1494.88,1778.35 C31.1@1536.42,1819.88 1536.42,1864.17 1462.01,1938.58 C4.1@1090.68,1938.58 891.6,2137.66 ; C6.1@1405.67,1743.72 ccw(c1490.3,1828.34) U3.3@1490.3,1708.66 ; 1473.71,1926.88 cw(c1366.72,1819.88) 1518.03,1819.88 cw(c1473.64,1819.88) 1505.03,1788.5 ; U3.3@1494.88,1741.75 cw(c1600.77,1741.75) C31.1@1525.89,1816.62 ; 1494.88,1769.93 cw(c1545.01,1769.93) C31.1@1524.52,1815.68 ; 1542,1858.59 cw(c1503.28,1819.88) C31.1@1558.03,1819.88
  Top Layer w70: v1@708.75,2085.63 ccw(c684.52,2109.86) 718.79,2109.86 ; v1@708.75,2107.29 cw(c684.52,2083.05) 718.79,2083.05 ; 718.79,1865.16 U2.4@718.79,2157.89 ; 718.79,1919.86 cw(c1132.31,1919.86) U2.4@839.91,2212.26 ; 718.79,2088.85 cw(c963.31,2088.85) U2.4@790.41,2261.76 ; v1@772.25,2094.23 cw(c826.68,2102.24) 782.52,2135.06 ; 759.87,2083.14 cw(c801.65,2072.62) 779.54,2109.6 ccw(c801.65,2072.62) 759.87,2083.14
  Bottom Layer w20: 387.96,1151.57 396.65,1151.57 538.45,1009.78 568.88,1009.78 634.62,944.04 634.62,632.51 738.53,528.6 1079.04,528.6 1079.21,528.78 1203.47,528.78 1203.64,528.6 1624.74,528.6 1870.08,773.94 v2(1870.08,856.3) ; v2@1854.88,841.1 cw(c1818.18,804.4) 1870.08,804.4 cw(c1921.97,804.4) v2@1885.28,841.1
  Bottom Layer w30: v2@475.63,1941.53 cw(c435.81,1941.53) 463.97,1913.37 cw(c492.13,1885.21) v2@492.13,1925.03 ; v2(492.13,1941.53) 387.96,1837.36 387.96,1015 552.1,850.87 552.1,579.79 668.28,463.6 1105.96,463.6 1106.13,463.78 1176.55,463.78 1176.72,463.6 1651.67,463.6 1663.05,474.99 1757.65,474.99 1759.65,472.99 2677.71,472.99 v2(2736.22,531.5) ; v2@2719.72,531.5 cw(c2679.9,531.5) 2708.06,503.34 cw(c2736.22,475.18) v2@2736.22,515
  other v1: 697.92,2096.46 787.4,2096.46 877.17,2096.46 621.73,2186.53 956.21,2186.53 620.86,2301.36 956.21,2301.36 956.21,2400.03 620.86,2411.42
24V: C2.1 K2.2 K5.3 K8.3 R5.2 R25.2 U2.3 | length 11134.3
  Top Layer w20: 3332.97,407.19 3332.97,849.11 3752.25,1268.39 3752.25,2663.72 3664.03,2751.95 3582.68,2833.3 R5.2@3582.68,2875 ; R5.2@3572,2864.32 cw(c3546.23,2838.55) 3582.68,2838.55 cw(c3619.13,2838.55) R5.2@3593.35,2864.32
  Top Layer w30: C2.1@600.39,2579.72 663.19,2579.72 ; 660.19,2579.72 cw(c660.19,2531.45) U2.3@694.33,2565.58 ; U2.3@694.13,2565.79 ccw(c663.19,2538.41) 663.19,2579.72 ; U2.3@694.94,2547.97 ccw(c702.98,2556.01) U2.3@707.32,2545.51 ; U2.3@695.85,2573.23 cw(c684.38,2600.91) 663.19,2579.72 ; U2.3@697.64,2545.28 663.19,2579.72
  Top Layer w40: U2.3@697.64,2545.28 697.64,2615.11 ; R25.2@3173.37,667.91 3173.37,546.03 3315.85,403.54 3441.39,403.54 3582.68,262.26 K8.3@3582.68,157.48 ; K8.3@3554.39,185.76 ccw(c3486.11,254.05) 3582.68,254.05 ccw(c3679.25,254.05) K8.3@3610.96,185.76
  Top Layer w50: K2.2@624.86,3046.12 cw(c565.11,2986.37) 649.61,2986.37 cw(c734.1,2986.37) K2.2@674.36,3046.12 ; K2.2@649.61,3070.87 649.61,2826.77 697.64,2778.74 697.64,2615.11
  Bottom Layer w120: 442.91,511.81 576.12,378.6 1141.17,378.6 1141.34,378.78 1141.51,378.6 1686.88,378.6 1698.26,389.99 1722.44,389.99 ; 600.39,3021.65 K2.2@649.61,3070.87 ; K5.3@1633.86,157.48 1633.86,301.41 1722.44,389.99 ; 3527,291.9 cw(c3392.58,157.48) K8.3@3582.68,157.48 3582.68,236.22 3428.91,389.99 2714.92,389.99 2712.92,387.99 1724.44,387.99 1722.44,389.99
  Bottom Layer w150: 442.91,511.81 442.91,756.74 271.78,927.88 271.78,2693.04 600.39,3021.65
24V_GND: K2.1 K5.2 K8.2 NT1.1 NT3.1 NT4.1 | length 8257.5
  Top Layer w70: K2.1@821.46,3070.87 ccw(c761.1,3070.87) 803.78,3113.54 ccw(c846.46,3156.22) K2.1@846.46,3095.87 ; K2.1@846.46,3070.87 738.19,3179.13 237.88,3179.13 50.87,2992.13 50.87,1929.15 90.24,1889.78 90.24,1280.13 50.87,1240.76 50.87,108.27 108.27,50.87 1330.4,50.87 K5.2@1437.01,157.48 1543.61,50.87 3279.22,50.87 K8.2@3385.83,157.48 ; K5.2@1412.01,157.48 cw(c1351.65,157.48) 1394.33,114.8 cw(c1437.01,72.12) 1437.01,132.48 cw(c1437.01,72.12) 1479.69,114.8 cw(c1522.36,157.48) K5.2@1462.01,157.48 ; K8.2@3360.83,157.48 cw(c3300.47,157.48) 3343.15,114.8 cw(c3385.83,72.12) K8.2@3385.83,132.48
  Bottom Layer w15: NT1.1@1358.27,224.04 cw(c1358.27,194.62) 1379.07,215.42 ; NT1.1@1358.27,226.38 1368.11,226.38 ; 1368.11,226.37 ccw(c1413.48,271.74) K5.2@1426.42,208.9 ; K5.2@1385.59,168.07 ccw(c1322.75,181.01) 1368.11,226.38 ; K5.2@1400.28,165.04 ccw(c1355.39,174.29) 1387.8,206.69 ccw(c1420.2,239.1) K5.2@1429.45,194.21 ; K5.2@1437.01,157.48 1368.11,226.38
  Bottom Layer w15.75: K2.1@846.46,3070.87 895.67,3021.65 NT4.1@927.19,3021.65 ; NT3.1@3306.54,216.54 3326.77,216.54 K8.2@3385.83,157.48
485_RE/DE: IC1.2 IC1.3 R6.2 U1.47 | length 2099.1
  Top Layer w12: R6.2@1628.86,2568.6 cw(c1596.26,2535.99) 1642.36,2535.99 cw(c1688.47,2535.99) R6.2@1655.87,2568.6 ; IC1.3@1637.41,2506.53 ccw(c1625.46,2518.48) 1642.36,2518.48 ccw(c1659.26,2518.48) IC1.3@1647.31,2506.53 ; R6.2@1643.33,2585.57 cw(c1678.28,2550.62) 1678.28,2600.04 ; IC1.3@1647.31,2469.63 cw(c1659.26,2457.68) 1659.26,2474.58 cw(c1659.26,2491.48) IC1.3@1647.31,2479.53 ; R6.2@1651.81,2577.08 cw(c1707.25,2521.65) 1707.25,2600.04 ; R6.2@1660.3,2568.6 cw(c1736.22,2492.68) 1736.22,2600.04 ; IC1.2@1687.41,2469.63 ccw(c1675.46,2457.68) 1675.46,2474.58 ccw(c1675.46,2491.48) IC1.2@1687.41,2479.53 ; IC1.2@1692.36,2474.58 IC1.3@1642.36,2474.58 R6.2@1642.36,2582.1 1660.31,2600.04 2870.16,2600.04 3028.37,2441.84 3028.37,2341.88 U1.47@3006.65,2320.16 ; U1.47@3022.72,2344.45 ccw(c3009.08,2358.09) 3028.37,2358.09
485_RXD: U1.48
485_TXD: U1.49
Ext_Off1_2: D2.2 R30.1 R33.1 U1.43 | length 2243.4
  Top Layer w12: 2122.7,2664.93 2131.13,2656.5 2307.12,2656.5 2576.85,2926.23 2877.48,2926.23 3185.58,2618.12 ; 2134.11,2666.34 ccw(c2157.88,2690.11) 2157.88,2656.5 ; D2.2@2142.6,2674.83 ccw(c2186.85,2719.08) 2186.85,2656.5 ; U1.43@3095.73,2231.07 3152.27,2287.61 3232.59,2287.61 3296.46,2351.49 3296.46,2476.78 R30.1@3185.58,2587.65 ; U1.43@3115.91,2257.07 ccw(c3115.91,2271.1) 3125.83,2261.18 ccw(c3135.75,2251.26) U1.43@3121.72,2251.26 ; 3147.21,2656.5 cw(c3088.36,2597.65) R30.1@3171.58,2597.65 ; 3167.69,2636.01 cw(c3129.33,2597.65) R30.1@3183.58,2597.65 ; R30.1@3185.58,2563.65 cw(c3185.58,2505.71) 3226.55,2546.68 ; R30.1@3185.58,2575.65 cw(c3185.58,2546.68) 3206.07,2567.17
  Top Layer w25: R33.1@1991.58,2664.93 2122.7,2664.93
Ext_Off2_2: D2.1 R31.1 R32.1 U1.42 | length 2253.9
  Top Layer w12: 2122.7,2738.93 2125.32,2741.55 2319.7,2741.55 2526.38,2948.23 2897.64,2948.23 3329.28,2516.59 3329.28,2346.6 3325,2342.33 ; D2.1@2142.6,2729.03 cw(c2172.83,2698.8) 2172.83,2741.55 ; 2142.6,2748.83 ccw(c2160.16,2766.4) 2160.16,2741.55 ; U1.42@3118,2208.8 3174.81,2265.61 3248.29,2265.61 3325,2342.33 ; U1.42@3138.18,2234.8 ccw(c3138.18,2248.83) 3148.1,2238.91 ccw(c3158.02,2228.99) U1.42@3144,2228.99 ; R31.1@3317.64,2305.74 ccw(c3299.89,2323.5) 3325,2323.5 ; R31.1@3325,2288.39 3325,2342.33 ; 3325,2335.78 ccw(c3367.49,2335.78) R31.1@3337.44,2305.74
  Top Layer w25: R32.1@1988.58,2738.93 2122.7,2738.93 ; R32.1@1993.89,2728.77 cw(c2018.41,2704.25) 2018.41,2738.93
